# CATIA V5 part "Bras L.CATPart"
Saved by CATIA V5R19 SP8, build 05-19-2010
Part number: Bras L
Revision: ANY
Definition: UNKNOWN
Nomenclature: Bras L
Source: Unknown
Bounding box of the stored display mesh (mm): x -17 to 283.131, y -15.75 to 8.75, z -28.516 to 11.516
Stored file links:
  D:\Documents\1_Travail\1 - ac-limoges.fr\OneDrive - ac-limoges.fr\STI2D_Turgot\2 -2I2D\3_SEQUENCE_Serre_Connectée\3- Spécificités\ITEC\EC 3 Ouverture automatique\Simulation  Ouverture Automatique\Bras L.CATPart
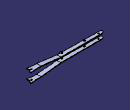
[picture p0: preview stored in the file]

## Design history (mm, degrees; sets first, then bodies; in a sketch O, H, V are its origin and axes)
Body1 "NONE" (main body)
  Solid1: solid without history
Body2 "NONE"
  Solid2: solid without history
